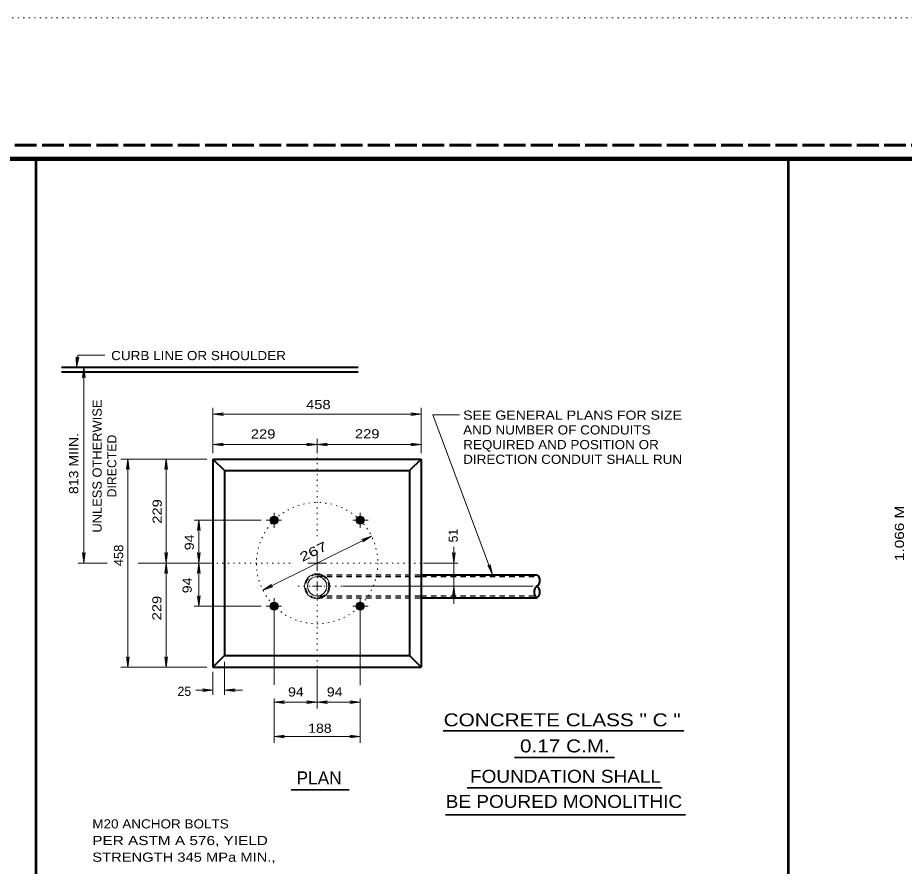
# Model space of a CAD drawing. Extents: x 312583 to 312854, y 144419 to 144597.
# Drawn here: x 312690.4 to 312763.9, y 144526.5 to 144596.8 of the extents above; entities that cross this region are included whole.
import ezdxf
from ezdxf.enums import TextEntityAlignment as Align

# ---------------------------------------------------------------- set-up
doc = ezdxf.new("R2010")
doc.units = 0
doc.header["$LTSCALE"] = 0.3
for name, pattern in [('DOTTED', [1.5, 0.3, -1.2]), ('LONG_DASHED', [7.5, 6, -1.5]), ('SHORT_DASHED', [2.7, 1.5, -1.2])]:
    doc.linetypes.add(name, pattern=pattern)
for name, color, linetype, lineweight in [('1', 7, 'Continuous', 25), ('2', 7, 'Continuous', 13), ('62', 7, 'DOTTED', 13), ('63', 7, 'LONG_DASHED', 60)]:
    doc.layers.add(name, color=color, linetype=linetype, lineweight=lineweight)

msp = doc.modelspace()

# ---------------------------------------------------------------- linework, layer by layer
at = {"layer": '1', "lineweight": 53}
for p, q in [((312691.9772, 144423.0846), (312691.9772, 144585.0846)), ((312754.2862, 144423.0846), (312754.2862, 144585.0846))]:
    msp.add_line(p, q, dxfattribs=at)
at = {"layer": '1', "lineweight": 40}
for p, q in [((312718.6466, 144567.8106), (312694.0519, 144567.8106)), ((312718.6466, 144567.4042), (312694.0519, 144567.4042)), ((312706.6099, 144560.2129), (312723.8599, 144560.2129)), ((312706.6099, 144560.2129), (312706.6099, 144542.9629)), ((312706.6099, 144560.2129), (312707.5683, 144559.2546)), ((312722.9016, 144559.2546), (312723.8599, 144560.2129)), ((312723.8599, 144560.2129), (312723.8599, 144542.9629)), ((312707.5683, 144559.2546), (312707.5683, 144543.9212)), ((312723.8599, 144550.6296), (312733.4433, 144550.6296)), ((312723.8599, 144548.7129), (312733.4433, 144548.7129)), ((312707.5683, 144543.9212), (312706.6099, 144542.9629)), ((312707.5683, 144543.9212), (312722.9016, 144543.9212)), ((312722.9016, 144543.9212), (312723.8599, 144542.9629)), ((312706.6099, 144542.9629), (312723.8599, 144542.9629))]:
    msp.add_line(p, q, dxfattribs=at)
at = {"layer": '1', "linetype": 'SHORT_DASHED'}
for p, q in [((312715.2349, 144550.6296), (312723.8599, 144550.6296)), ((312715.2349, 144548.7129), (312723.8599, 144548.7129))]:
    msp.add_line(p, q, dxfattribs=at)
at = {"layer": '1', "lineweight": 158}
msp.add_lwpolyline([(312616.5, 144423.1446), (312616.5, 144585.0846), (312849, 144585.0846)], dxfattribs=at)
at = {"layer": '1', "lineweight": 40}
msp.add_lwpolyline([(312707.5683, 144559.2546), (312722.9016, 144559.2546), (312722.9016, 144543.9212)], dxfattribs=at)
at = {"layer": '1', "linetype": 'SHORT_DASHED'}
for points in [[(312715.2349, 144550.4686), (312723.8599, 144550.4686), (312733.5966, 144550.4686)], [(312715.2349, 144548.8739), (312723.8599, 144548.8739), (312733.2976, 144548.8739)]]:
    msp.add_lwpolyline(points, dxfattribs=at)
at = {"layer": '1', "linetype": 'DOTTED', "lineweight": 13}
msp.add_circle((312715.2378, 144551.5879), 5.0312, dxfattribs=at)
at = {"layer": '1', "lineweight": 40}
for centre, radius in [((312711.6738, 144555.1519), 0.2995), ((312711.6738, 144555.1519), 0.2396), ((312711.6738, 144555.1519), 0.1917), ((312711.6738, 144555.1519), 0.1533), ((312711.6738, 144555.1519), 0.1227), ((312718.8018, 144555.1519), 0.2995), ((312718.8018, 144555.1519), 0.2396), ((312718.8018, 144555.1519), 0.1917), ((312718.8018, 144555.1519), 0.1533), ((312718.8018, 144555.1519), 0.1227), ((312711.6738, 144555.1519), 0.0981), ((312711.6738, 144555.1519), 0.0785), ((312711.6738, 144555.1519), 0.0628), ((312711.6738, 144555.1519), 0.0502), ((312718.8018, 144555.1519), 0.0981), ((312718.8018, 144555.1519), 0.0785), ((312718.8018, 144555.1519), 0.0628), ((312718.8018, 144555.1519), 0.0502), ((312711.6738, 144548.0239), 0.2995), ((312711.6738, 144548.0239), 0.2396), ((312711.6738, 144548.0239), 0.1917), ((312711.6738, 144548.0239), 0.1533), ((312711.6738, 144548.0239), 0.1227), ((312711.6738, 144548.0239), 0.0981), ((312711.6738, 144548.0239), 0.0785), ((312711.6738, 144548.0239), 0.0628), ((312711.6738, 144548.0239), 0.0502), ((312718.8018, 144548.0239), 0.2995), ((312718.8018, 144548.0239), 0.2396), ((312718.8018, 144548.0239), 0.1917), ((312718.8018, 144548.0239), 0.1533), ((312718.8018, 144548.0239), 0.1227), ((312718.8018, 144548.0239), 0.0981), ((312718.8018, 144548.0239), 0.0785), ((312718.8018, 144548.0239), 0.0628), ((312718.8018, 144548.0239), 0.0502)]:
    msp.add_circle(centre, radius, dxfattribs=at)
at = {"layer": '1', "lineweight": 13}
for radius in [1.0379, 0.7983]:
    msp.add_circle((312715.2378, 144549.6712), radius, dxfattribs=at)
at = {"layer": '1', "linetype": 'SHORT_DASHED', "lineweight": 13}
msp.add_circle((312715.2378, 144549.6712), 0.9583, dxfattribs=at)
at = {"layer": '1', "lineweight": 40}
for centre, start, end in [((312733.0898, 144550.1504), 306.63911, 53.36089), ((312733.8025, 144549.1921), 126.63911, 233.36089), ((312733.0898, 144549.1921), 306.63911, 53.36089)]:
    msp.add_arc(centre, 0.5972, start, end, dxfattribs=at)
at = {"layer": '2'}
for p, q in [((312695.2863, 144568.6846), (312695.3706, 144568.3932)), ((312695.3093, 144567.8106), (312695.2863, 144568.6846)), ((312695.3093, 144567.8106), (312695.5009, 144568.6616)), ((312695.5009, 144568.6616), (312695.3706, 144568.3932)), ((312695.9073, 144567.8106), (312695.7999, 144566.9442)), ((312695.9073, 144551.5879), (312695.9073, 144567.8106)), ((312695.9073, 144567.8106), (312696.0146, 144566.9442)), ((312695.7999, 144566.9442), (312695.9073, 144567.2202)), ((312696.0146, 144566.9442), (312695.9073, 144567.2202)), ((312706.6099, 144560.7036), (312706.6099, 144564.4526)), ((312723.8599, 144560.7036), (312723.8599, 144564.4526)), ((312706.6099, 144563.9312), (312707.4763, 144564.0386)), ((312706.6099, 144563.9312), (312723.8599, 144563.9312)), ((312706.6099, 144563.9312), (312707.4763, 144563.8239)), ((312707.4763, 144564.0386), (312707.2003, 144563.9312)), ((312707.4763, 144563.8239), (312707.2003, 144563.9312)), ((312722.9936, 144564.0386), (312723.2696, 144563.9312)), ((312723.8599, 144563.9312), (312722.9936, 144564.0386)), ((312722.9936, 144563.8239), (312723.2696, 144563.9312)), ((312723.8599, 144563.9312), (312722.9936, 144563.8239)), ((312724.8106, 144563.8776), (312727.0416, 144563.8776)), ((312729.7633, 144550.6296), (312724.8106, 144563.8776)), ((312715.2349, 144560.7036), (312715.2349, 144561.8919)), ((312706.6099, 144561.4166), (312707.4763, 144561.5239)), ((312706.6099, 144561.4166), (312707.4763, 144561.3092)), ((312707.4763, 144561.5239), (312707.2003, 144561.4166)), ((312707.4763, 144561.3092), (312707.2003, 144561.4166)), ((312714.3686, 144561.5239), (312714.6446, 144561.4166)), ((312715.2349, 144561.4166), (312714.3686, 144561.5239)), ((312714.3686, 144561.3092), (312714.6446, 144561.4166)), ((312715.2349, 144561.4166), (312714.3686, 144561.3092)), ((312715.2349, 144561.4166), (312716.1013, 144561.5239)), ((312715.2349, 144561.4166), (312716.1013, 144561.3092)), ((312716.1013, 144561.5239), (312715.8253, 144561.4166)), ((312716.1013, 144561.3092), (312715.8253, 144561.4166)), ((312722.9936, 144561.5239), (312723.2696, 144561.4166)), ((312723.8599, 144561.4166), (312722.9936, 144561.5239)), ((312722.9936, 144561.3092), (312723.2696, 144561.4166)), ((312723.8599, 144561.4166), (312722.9936, 144561.3092)), ((312706.1039, 144560.2129), (312698.9893, 144560.2129)), ((312699.5566, 144560.2129), (312699.4493, 144559.3466)), ((312699.5566, 144542.9629), (312699.5566, 144560.2129)), ((312699.5566, 144560.2129), (312699.6639, 144559.3466)), ((312702.7383, 144560.2129), (312702.6309, 144559.3466)), ((312702.7383, 144560.2129), (312702.8456, 144559.3466)), ((312699.4493, 144559.3466), (312699.5566, 144559.6226)), ((312699.6639, 144559.3466), (312699.5566, 144559.6226)), ((312702.6309, 144559.3466), (312702.7383, 144559.6226)), ((312702.8456, 144559.3466), (312702.7383, 144559.6226)), ((312711.6776, 144554.5012), (312711.6776, 144555.7586)), ((312718.7999, 144554.5012), (312718.7999, 144555.7586)), ((312710.6119, 144555.1529), (312705.0613, 144555.1529)), ((312705.4446, 144555.1529), (312705.3373, 144554.2866)), ((312705.3373, 144554.2866), (312705.4446, 144554.5626)), ((312705.4446, 144555.1529), (312705.5519, 144554.2866)), ((312705.5519, 144554.2866), (312705.4446, 144554.5626)), ((312712.2909, 144555.1529), (312711.0106, 144555.1529)), ((312718.1866, 144555.1529), (312719.4669, 144555.1529)), ((312710.7346, 144549.3416), (312719.7429, 144553.8342)), ((312719.7429, 144553.8342), (312718.9149, 144553.5429)), ((312719.7429, 144553.8342), (312719.0146, 144553.3512)), ((312718.9149, 144553.5429), (312719.2139, 144553.5659)), ((312719.0146, 144553.3512), (312719.2139, 144553.5659)), ((312695.7999, 144552.4542), (312695.9073, 144552.1782)), ((312695.9073, 144551.5879), (312695.7999, 144552.4542)), ((312696.0146, 144552.4542), (312695.9073, 144552.1782)), ((312695.9073, 144551.5879), (312696.0146, 144552.4542)), ((312702.6309, 144552.4542), (312702.7383, 144552.1782)), ((312702.7383, 144551.5879), (312702.6309, 144552.4542)), ((312702.8456, 144552.4542), (312702.7383, 144552.1782)), ((312702.7383, 144551.5879), (312702.8456, 144552.4542)), ((312705.3373, 144552.4542), (312705.4446, 144552.1782)), ((312705.4446, 144551.5879), (312705.3373, 144552.4542)), ((312705.5519, 144552.4542), (312705.4446, 144552.1782)), ((312705.4446, 144551.5879), (312705.5519, 144552.4542)), ((312715.2349, 144551.5879), (312715.2349, 144552.3546)), ((312726.4513, 144552.4542), (312726.5586, 144552.1782)), ((312726.5586, 144551.5879), (312726.4513, 144552.4542)), ((312726.5586, 144548.2069), (312726.5586, 144552.9449)), ((312726.6659, 144552.4542), (312726.5586, 144552.1782)), ((312726.5586, 144551.5879), (312726.6659, 144552.4542)), ((312697.8393, 144551.5879), (312695.4396, 144551.5879)), ((312706.4183, 144551.5879), (312700.4153, 144551.5879)), ((312702.7383, 144551.5879), (312702.6309, 144550.7216)), ((312702.7383, 144551.5879), (312702.8456, 144550.7216)), ((312705.4446, 144551.5879), (312705.3373, 144550.7216)), ((312705.4446, 144551.5879), (312705.5519, 144550.7216)), ((312715.2349, 144551.5879), (312714.4683, 144551.5879)), ((312715.2349, 144551.5879), (312716.0016, 144551.5879)), ((312715.2349, 144551.5879), (312715.2349, 144550.9439)), ((312724.0516, 144551.5879), (312726.8959, 144551.5879)), ((312726.5586, 144551.5879), (312726.5586, 144552.2242)), ((312702.6309, 144550.7216), (312702.7383, 144550.9976)), ((312702.8456, 144550.7216), (312702.7383, 144550.9976)), ((312705.3373, 144550.7216), (312705.4446, 144550.9976)), ((312705.5519, 144550.7216), (312705.4446, 144550.9976)), ((312729.3646, 144551.4039), (312729.5563, 144551.1816)), ((312729.7633, 144550.6296), (312729.3646, 144551.4039)), ((312729.5639, 144551.4806), (312729.5563, 144551.1816)), ((312729.7633, 144550.6296), (312729.5639, 144551.4806)), ((312710.7346, 144549.3416), (312711.4629, 144549.8246)), ((312710.7346, 144549.3416), (312711.5549, 144549.6329)), ((312711.4629, 144549.8246), (312711.2636, 144549.6099)), ((312711.5549, 144549.6329), (312711.2636, 144549.6099)), ((312715.2349, 144549.6712), (312714.8516, 144549.6712)), ((312715.2349, 144549.6712), (312715.2349, 144550.0546)), ((312715.2349, 144549.6712), (312715.6183, 144549.6712)), ((312715.2349, 144549.6712), (312715.2349, 144549.2879)), ((312717.3739, 144549.6712), (312733.1213, 144549.6712)), ((312726.5586, 144549.6712), (312726.4513, 144548.8049)), ((312726.5586, 144549.6712), (312726.6659, 144548.8049)), ((312705.3373, 144548.8892), (312705.4446, 144548.6132)), ((312705.4446, 144548.0229), (312705.3373, 144548.8892)), ((312705.5519, 144548.8892), (312705.4446, 144548.6132)), ((312705.4446, 144548.0229), (312705.5519, 144548.8892)), ((312711.6776, 144548.6746), (312711.6776, 144547.4172)), ((312718.7999, 144548.6746), (312718.7999, 144547.4172)), ((312726.4513, 144548.8049), (312726.5586, 144549.0809)), ((312726.6659, 144548.8049), (312726.5586, 144549.0809)), ((312710.6119, 144548.0229), (312705.0613, 144548.0229)), ((312712.2909, 144548.0229), (312711.0106, 144548.0229)), ((312718.1866, 144548.0229), (312719.4669, 144548.0229)), ((312711.6776, 144547.4172), (312711.6776, 144541.5139)), ((312718.7999, 144547.4172), (312718.7999, 144541.4679)), ((312699.4493, 144543.8292), (312699.5566, 144543.5532)), ((312699.5566, 144542.9629), (312699.4493, 144543.8292)), ((312699.6639, 144543.8292), (312699.5566, 144543.5532)), ((312699.5566, 144542.9629), (312699.6639, 144543.8292)), ((312702.6309, 144543.8292), (312702.7383, 144543.5532)), ((312702.7383, 144542.9629), (312702.6309, 144543.8292)), ((312702.8456, 144543.8292), (312702.7383, 144543.5532)), ((312702.7383, 144542.9629), (312702.8456, 144543.8292)), ((312706.1039, 144542.9629), (312698.9893, 144542.9629)), ((312707.5683, 144543.4152), (312707.5683, 144540.6706)), ((312706.6099, 144542.5719), (312706.6099, 144540.6706)), ((312715.2349, 144542.7712), (312715.2349, 144539.5436)), ((312705.1763, 144541.0616), (312706.6099, 144541.0616)), ((312705.7436, 144541.1689), (312706.0196, 144541.0616)), ((312706.6099, 144541.0616), (312705.7436, 144541.1689)), ((312705.7436, 144540.9542), (312706.0196, 144541.0616)), ((312706.6099, 144541.0616), (312705.7436, 144540.9542)), ((312707.5683, 144541.0616), (312708.4346, 144541.1689)), ((312707.5683, 144541.0616), (312709.0633, 144541.0616)), ((312707.5683, 144541.0616), (312708.4346, 144540.9542)), ((312708.4346, 144541.1689), (312708.1586, 144541.0616)), ((312708.4346, 144540.9542), (312708.1586, 144541.0616)), ((312711.6776, 144540.3562), (312711.6776, 144536.6916)), ((312711.6776, 144540.0649), (312712.5439, 144540.1722)), ((312711.6776, 144540.0649), (312712.5439, 144539.9576)), ((312712.5439, 144540.1722), (312712.2679, 144540.0649)), ((312712.5439, 144539.9576), (312712.2679, 144540.0649)), ((312714.3686, 144540.1722), (312714.6446, 144540.0649)), ((312715.2349, 144540.0649), (312714.3686, 144540.1722)), ((312714.3686, 144539.9576), (312714.6446, 144540.0649)), ((312715.2349, 144540.0649), (312714.3686, 144539.9576)), ((312715.2349, 144540.0649), (312716.1013, 144540.1722)), ((312715.2349, 144540.0649), (312716.1013, 144539.9576)), ((312716.1013, 144540.1722), (312715.8253, 144540.0649)), ((312716.1013, 144539.9576), (312715.8253, 144540.0649)), ((312717.9336, 144540.1722), (312718.2096, 144540.0649)), ((312718.7999, 144540.0649), (312717.9336, 144540.1722)), ((312717.9336, 144539.9576), (312718.2096, 144540.0649)), ((312718.7999, 144540.0649), (312717.9336, 144539.9576)), ((312718.7999, 144540.3716), (312718.7999, 144536.6916)), ((312711.6776, 144537.2129), (312712.5439, 144537.3202)), ((312711.6776, 144537.2129), (312718.7999, 144537.2129)), ((312711.6776, 144537.2129), (312712.5439, 144537.1056)), ((312712.5439, 144537.3202), (312712.2679, 144537.2129)), ((312712.5439, 144537.1056), (312712.2679, 144537.2129)), ((312717.9336, 144537.3202), (312718.2096, 144537.2129)), ((312718.7999, 144537.2129), (312717.9336, 144537.3202)), ((312717.9336, 144537.1056), (312718.2096, 144537.2129)), ((312718.7999, 144537.2129), (312717.9336, 144537.1056))]:
    msp.add_line(p, q, dxfattribs=at)
at = {"layer": '2', "linetype": 'DOTTED'}
for p, q in [((312715.2349, 144553.8112), (312715.2349, 144560.4046)), ((312713.0039, 144551.5879), (312706.4183, 144551.5879)), ((312716.3849, 144551.5879), (312724.0516, 144551.5879)), ((312715.2349, 144550.4379), (312715.2349, 144550.1312)), ((312714.6599, 144549.6712), (312713.2723, 144549.6712)), ((312715.8099, 144549.6712), (312717.3739, 144549.6712)), ((312715.2349, 144549.0579), (312715.2349, 144542.7712))]:
    msp.add_line(p, q, dxfattribs=at)
at = {"layer": '2', "lineweight": 35}
for p, q in [((312725.6739, 144537.6811), (312745.6191, 144537.6811)), ((312731.5752, 144535.4755), (312739.867, 144535.4755)), ((312713.0846, 144532.8139), (312717.8979, 144532.8139)), ((312727.6729, 144532.978), (312743.8084, 144532.978)), ((312725.8801, 144530.7351), (312745.7506, 144530.7351))]:
    msp.add_line(p, q, dxfattribs=at)
at = {"layer": '2'}
for points in [[(312697.6629, 144568.8226), (312695.4089, 144568.8226), (312695.3093, 144567.8106)], [(312706.6099, 144561.4166), (312715.2349, 144561.4166), (312723.8599, 144561.4166)], [(312702.7383, 144542.9629), (312702.7383, 144551.5879), (312702.7383, 144560.2129)], [(312705.4446, 144548.0229), (312705.4446, 144551.5879), (312705.4446, 144555.1529)], [(312711.6776, 144540.0649), (312715.2349, 144540.0649), (312718.7999, 144540.0649)]]:
    msp.add_lwpolyline(points, dxfattribs=at)
at = {"layer": '62'}
msp.add_line((312601.2, 144596.7846), (312853.5, 144596.7846), dxfattribs=at)
at = {"layer": '63'}
msp.add_line((312851.75, 144586.2246), (312583.526, 144586.2246), dxfattribs=at)

# ---------------------------------------------------------------- texts
at = {"layer": '2'}
for s, width, p in [('CURB LINE OR SHOULDER', 1.1, (312698.1759, 144568.4094)), ('458 ', 1.2, (312714.3201, 144564.3502)), ('SEE GENERAL PLANS FOR SIZE', 1.15, (312727.3329, 144563.4702)), ('229 ', 1.2, (312709.7454, 144561.9132)), ('229 ', 1.2, (312718.3682, 144561.9251)), ('AND NUMBER OF CONDUITS', 1.1, (312727.3329, 144562.2502)), ('REQUIRED AND POSITION OR', 1.1, (312727.3329, 144561.0302)), ('DIRECTION CONDUIT SHALL RUN', 1.1, (312727.3329, 144559.8102)), ('94 ', 1.15, (312712.8306, 144540.5348)), ('94 ', 1.15, (312716.0387, 144540.5348)), ('188 ', 1.15, (312714.4917, 144537.524)), ('M20 ANCHOR BOLTS', 1.1, (312696.6125, 144529.6004)), ('PER ASTM A 576, YIELD', 1.25, (312696.6125, 144528.2204)), ('STRENGTH 345 MPa MIN., ', 1.2, (312696.6125, 144526.8404))]:
    msp.add_text(s, height=0.76, dxfattribs=dict(at, width=width)).set_placement(p)
at = {"layer": '2', "width": 1.05}
msp.add_text('UNLESS OTHERWISE', height=0.76, rotation=90, dxfattribs=at).set_placement((312697.3922, 144559.6315), align=Align.CENTER)
at = {"layer": '2'}
for s, rotation, width, p in [('813 MIIN.', 90, 1.15, (312695.453, 144557.3112)), ('229 ', 90, 1.2, (312702.3672, 144554.8512)), ('1.066 M', 90, 1.25, (312763.8478, 144551.7575)), ('94 ', 90, 1.15, (312705.0274, 144552.6567)), ('458', 90, 1.05, (312699.177, 144551.3347)), ('267 ', 26, 1.4, (312714.0175, 144551.6829)), ('94 ', 90, 1.15, (312704.8497, 144549.0927)), ('229 ', 90, 1.2, (312702.3417, 144546.8454))]:
    msp.add_text(s, height=0.76, rotation=rotation, dxfattribs=dict(at, width=width)).set_placement(p)
msp.add_text('DIRECTED', height=0.76, rotation=90, dxfattribs=at).set_placement((312698.6122, 144559.6315), align=Align.CENTER)
msp.add_text('51 ', height=0.76, rotation=90, dxfattribs=at).set_placement((312726.8852, 144553.3028))
msp.add_text('25', height=0.76, dxfattribs=at).set_placement((312703.6735, 144540.5873))
for s, width, p in [('CONCRETE CLASS " C "', 1.2, (312735.536, 144538.064)), ('0.17 C.M.', 1.2, (312735.7618, 144535.903)), ('FOUNDATION SHALL', 1.1, (312735.8099, 144533.3874)), ('BE POURED MONOLITHIC', 1.1, (312735.6801, 144531.3022))]:
    msp.add_text(s, height=1.07, dxfattribs=dict(at, width=width)).set_placement(p, align=Align.CENTER)
msp.add_text('PLAN', height=1.07, dxfattribs=at).set_placement((312715.4013, 144533.2546), align=Align.CENTER)

doc.saveas('drawing.dxf')
